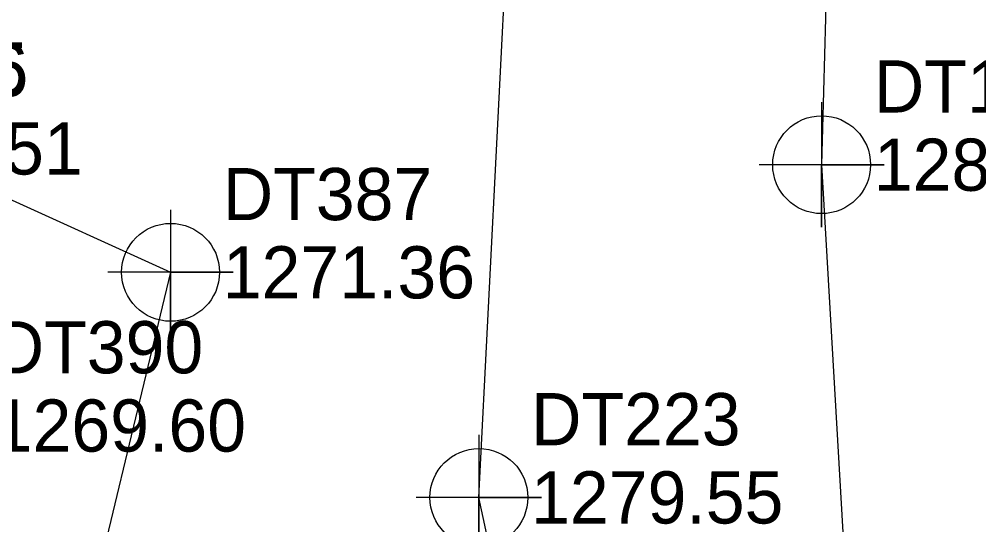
# Model space of a CAD drawing. Extents: x 1391270 to 1392151, y 960049 to 960667.
# Drawn here: x 1391650.74 to 1391696.71, y 960347.9 to 960372.13 of the extents above; entities that cross this region are included whole.
import ezdxf

# ---------------------------------------------------------------- set-up
doc = ezdxf.new("R2010")
doc.units = 0
for name, color, linetype in [('Exist DTM Breakline', 7, 'Continuous'), ('Exist DTM Breakline Cogo Comment', 7, 'Continuous'), ('Exist DTM Breakline Cogo Elevation', 7, 'Continuous'), ('Exist DTM Breakline Cogo Number', 7, 'Continuous'), ('Exist DTM Breakline Cogo Point CELL', 7, 'Continuous')]:
    doc.layers.add(name, color=color, linetype=linetype)

msp = doc.modelspace()

# ---------------------------------------------------------------- linework, layer by layer
at = {"layer": 'Exist DTM Breakline'}
for p, q in [((1391636.562, 960369.763), (1391657.996, 960360)), ((1391657.996, 960360), (1391653.858, 960342.787))]:
    msp.add_line(p, q, dxfattribs=at)
for points in [[(1391677.683, 960326.497), (1391672.764, 960349.215), (1391674.149, 960376.543), (1391679.962, 960405.823), (1391686.399, 960436.645)], [(1391689.894, 960391.525), (1391689.18, 960365.157), (1391690.906, 960335.168), (1391693.62, 960320.244), (1391696.803, 960298.575), (1391694.311, 960295.44), (1391699.762, 960289.791)]]:
    msp.add_lwpolyline(points, dxfattribs=at)
at = {"layer": 'Exist DTM Breakline Cogo Point CELL'}
for points in [[(1391689.18, 960368.157), (1391689.18, 960362.157), (1391689.18, 960365.157), (1391692.18, 960365.157), (1391686.18, 960365.157)], [(1391657.996, 960363), (1391657.996, 960357), (1391657.996, 960360), (1391660.996, 960360), (1391654.996, 960360)], [(1391672.764, 960352.215), (1391672.764, 960346.215), (1391672.764, 960349.215), (1391675.764, 960349.215), (1391669.764, 960349.215)]]:
    msp.add_lwpolyline(points, dxfattribs=at)
for centre in [(1391689.18, 960365.157), (1391657.996, 960360), (1391672.764, 960349.215)]:
    msp.add_circle(centre, 2.344, dxfattribs=at)

# ---------------------------------------------------------------- texts
at = {"layer": 'Exist DTM Breakline Cogo Comment'}
msp.add_text('*BL40051', height=2.5, dxfattribs=at).set_placement((1391639.099, 960364.686))
at = {"layer": 'Exist DTM Breakline Cogo Elevation'}
for s, p in [('1266.05', (1391639.062, 960368.513)), ('1266.06', (1391639.099, 960368.436)), ('1282.38', (1391691.68, 960363.907)), ('1271.36', (1391660.496, 960358.75)), ('1269.60', (1391649.525, 960351.41)), ('1279.55', (1391675.264, 960347.965))]:
    msp.add_text(s, height=2.5, dxfattribs=at).set_placement(p)
at = {"layer": 'Exist DTM Breakline Cogo Number'}
for s, p in [('DT194', (1391691.68, 960367.657)), ('DT387', (1391660.496, 960362.5)), ('DT390', (1391649.525, 960355.16)), ('DT223', (1391675.264, 960351.715))]:
    msp.add_text(s, height=2.5, dxfattribs=at).set_placement(p)

doc.saveas('drawing.dxf')
